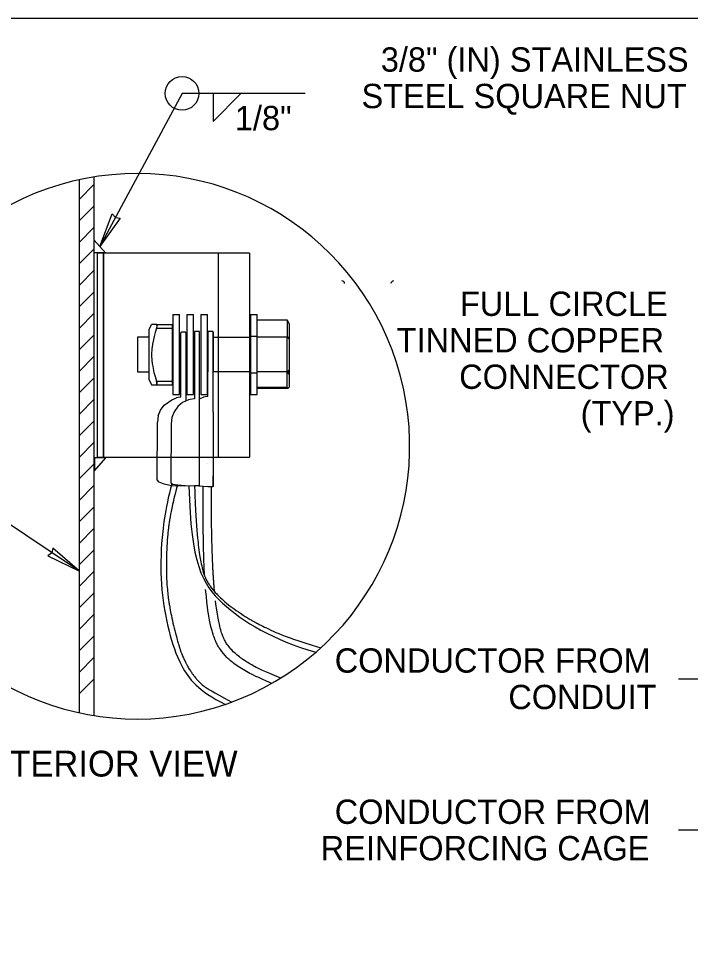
# Model space of a CAD drawing. Extents: x 99862 to 103680, y 99470 to 105076.
# Drawn here: x 101525 to 101968, y 104466 to 105076 of the extents above; entities that cross this region are included whole.
import ezdxf

# ---------------------------------------------------------------- set-up
doc = ezdxf.new("R2010")
doc.units = 0
for name, color, linetype in [('Level 1', 7, 'Continuous'), ('Level 10', 7, 'Continuous'), ('Level 11', 7, 'Continuous'), ('Level 12', 7, 'Continuous'), ('Level 14', 7, 'Continuous'), ('Level 15', 7, 'Continuous'), ('Level 18', 7, 'Continuous'), ('Level 2', 7, 'Continuous'), ('Level 20', 7, 'Continuous'), ('Level 21', 7, 'Continuous'), ('Level 3', 7, 'Continuous'), ('Level 34', 7, 'Continuous'), ('Level 4', 7, 'Continuous')]:
    doc.layers.add(name, color=color, linetype=linetype)

msp = doc.modelspace()

# ---------------------------------------------------------------- linework, layer by layer
at = {"layer": 'Level 1'}
for p, q in [((101577.19, 104921.26), (101577.21, 104921.26)), ((101577.19, 104921.26), (101577.19, 104786.96)), ((101581.33, 104921.26), (101581.33, 104786.96)), ((101656.72, 104921.26), (101656.72, 104786.96)), ((101677.39, 104921.26), (101677.39, 104786.96)), ((101677.39, 104843.2), (101653.49, 104843.2)), ((101577.21, 104786.96), (101577.19, 104786.96))]:
    msp.add_line(p, q, dxfattribs=at)
msp.add_lwpolyline([(99862, 102999.5), (103151, 102999.5), (103151, 105075.5), (99862, 105075.5)], close=True, dxfattribs=at)
for points in [[(101677.39, 104921.26), (101677.21, 104921.26), (101675.26, 104921.26), (101670.68, 104921.26), (101664.21, 104921.26), (101656.72, 104921.26), (101581.33, 104921.26), (101577.21, 104921.26), (101577.21, 104786.96), (101581.33, 104786.96), (101616.78, 104786.96)], [(101581.31, 104786.96), (101581.31, 104786.96), (101581.31, 104921.26), (101581.31, 104921.26)], [(101677.39, 104865.75), (101677.39, 104865.75), (101653.49, 104865.75)], [(101653.48, 104786.96), (101656.72, 104786.96), (101664.21, 104786.96), (101670.68, 104786.96), (101675.26, 104786.96), (101677.21, 104786.96), (101677.39, 104786.96)]]:
    msp.add_lwpolyline(points, dxfattribs=at)
at = {"layer": 'Level 10'}
for centre, start, end in [((101738.25, 104901.12), 0, 90), ((101772.28, 104901.12), 90, 180)]:
    msp.add_arc(centre, 1.8, start, end, dxfattribs=at)
at = {"layer": 'Level 11'}
for points in [[(101626.26, 104769.75), (101621.67, 104751.55), (101618.9, 104729.68), (101618.9, 104699.44), (101624.29, 104671.59), (101631.13, 104649.94), (101643.4, 104633.25), (101661.68, 104624.31)], [(101629.99, 104768.75), (101627.65, 104759.73), (101626.15, 104752.94), (101624.84, 104745.62), (101624.58, 104743.99), (101624.26, 104741.74), (101624.17, 104741.03), (101623.99, 104739.58), (101623.57, 104735.89), (101623.26, 104731.95), (101622.89, 104725.34), (101622.77, 104721.87), (101622.72, 104717.33), (101622.71, 104716.42), (101622.7, 104715.03), (101622.7, 104714.56), (101622.71, 104713.64), (101622.72, 104711.33), (101622.89, 104705.41), (101623.32, 104700.07), (101623.94, 104694.82), (101624.29, 104692.21), (101624.78, 104689.21), (101625.05, 104687.72), (101625.17, 104687.08), (101625.25, 104686.66), (101625.29, 104686.45), (101626.66, 104679.36), (101628.12, 104673.08), (101630.1, 104665.97), (101630.61, 104664.24), (101631.12, 104662.57), (101631.28, 104662.07), (101631.33, 104661.91), (101631.43, 104661.59), (101631.69, 104660.79), (101631.96, 104660), (101633.08, 104656.88), (101634.1, 104654.49), (101636.39, 104649.92), (101637.67, 104647.73), (101639.41, 104645.13), (101639.77, 104644.62), (101640.32, 104643.86), (101640.5, 104643.6), (101640.87, 104643.12), (101641.79, 104641.91), (101642.73, 104640.81), (101645.04, 104638.33), (101646.65, 104636.92), (101649.89, 104634.63), (101651.53, 104633.71), (101665.78, 104625.74)], [(101637.55, 104768.23), (101638.8, 104716.73), (101653.49, 104690.38), (101693.08, 104666.73), (101721.07, 104658.71)], [(101641.33, 104768.15), (101641.64, 104756.84), (101642.1, 104747.46), (101643.15, 104734.4), (101643.62, 104729.91), (101644.71, 104721.95), (101645.32, 104718.47), (101646.66, 104712.55), (101647.4, 104710.11), (101648.33, 104707.77), (101648.52, 104707.34), (101648.8, 104706.75), (101648.89, 104706.56), (101649.08, 104706.2), (101649.17, 104706.03), (101649.32, 104705.77), (101649.37, 104705.67), (101649.48, 104705.48), (101649.64, 104705.2), (101650.03, 104704.55), (101650.39, 104703.98), (101652.61, 104700.59), (101655.19, 104697.54), (101661.6, 104691.44), (101665.44, 104688.38), (101672.13, 104683.81), (101674.52, 104682.29), (101677.69, 104680.4), (101678.33, 104680.03), (101679.63, 104679.29), (101681.61, 104678.19), (101683.67, 104677.1), (101695.56, 104671.12), (101708.15, 104666.36), (101724.43, 104661.68)]]:
    msp.add_open_spline(points, degree=3, dxfattribs=at)
at = {"layer": 'Level 12'}
for p, q in [((101565.46, 104956.78), (101574.95, 104966.27)), ((101565.46, 104942.63), (101574.95, 104952.13)), ((101565.46, 104928.49), (101574.95, 104937.99)), ((101565.46, 104914.35), (101574.95, 104923.85)), ((101565.46, 104900.21), (101574.95, 104909.71)), ((101565.46, 104886.06), (101574.95, 104895.56)), ((101565.46, 104871.92), (101574.95, 104881.42)), ((101565.46, 104857.78), (101574.95, 104867.28)), ((101565.46, 104843.64), (101574.95, 104853.14)), ((101565.46, 104829.5), (101574.95, 104838.99)), ((101565.46, 104815.35), (101574.95, 104824.85)), ((101565.46, 104801.21), (101574.95, 104810.71)), ((101565.46, 104787.07), (101574.95, 104796.57)), ((101565.46, 104772.93), (101574.95, 104782.43)), ((101565.46, 104758.79), (101574.95, 104768.28)), ((101565.46, 104744.64), (101574.95, 104754.14)), ((101565.46, 104730.5), (101574.95, 104740)), ((101565.46, 104716.36), (101574.95, 104725.86)), ((101565.46, 104702.22), (101574.95, 104711.72)), ((101565.46, 104688.07), (101574.95, 104697.57)), ((101565.46, 104673.93), (101574.95, 104683.43)), ((101565.46, 104659.79), (101574.95, 104669.29)), ((101565.46, 104645.65), (101574.95, 104655.15)), ((101565.46, 104631.51), (101574.95, 104641))]:
    msp.add_line(p, q, dxfattribs=at)
at = {"layer": 'Level 14'}
for p, q in [((101650, 104869.26), (101650, 104865.81)), ((101644.27, 104825.35), (101647.2, 104826.49)), ((101653.49, 104816.67), (101653.48, 104767.74)), ((101616.78, 104786.96), (101655.1, 104786.96)), ((101653.48, 104767.74), (101653.48, 104774.66)), ((101649.99, 104767.74), (101653.48, 104767.74))]:
    msp.add_line(p, q, dxfattribs=at)
for points in [[(101650, 104826.96), (101650, 104859.91), (101650, 104864.54), (101650, 104867.95), (101650, 104869.26)], [(101650, 104843.05), (101650, 104843.24), (101650, 104843.86), (101650, 104844.89), (101650, 104846.28), (101650, 104848), (101650, 104849.96), (101650, 104852.09), (101650, 104854.32), (101650, 104856.55), (101650, 104858.7), (101650, 104860.69), (101650, 104862.45), (101650, 104863.89), (101650, 104864.97), (101650, 104865.65), (101650, 104865.9)], [(101650, 104865.9), (101650, 104865.72), (101650, 104865.09), (101650, 104864.07), (101650, 104862.67), (101650, 104860.96), (101650, 104858.99), (101650, 104856.86), (101650, 104854.63), (101650, 104852.4), (101650, 104850.25), (101650, 104848.26), (101650, 104846.51), (101650, 104845.06), (101650, 104843.98), (101650, 104843.3), (101650, 104843.05)], [(101653.04, 104869.71), (101650.45, 104869.71)], [(101653.49, 104816.67), (101653.49, 104852.5), (101653.49, 104857.81), (101653.49, 104862.69), (101653.49, 104866.52), (101653.49, 104868.81), (101653.49, 104869.26)], [(101653.49, 104869.26), (101653.49, 104867.81), (101653.49, 104864.65), (101653.49, 104860.18)], [(101653.49, 104865.9), (101653.49, 104865.72), (101653.49, 104865.09), (101653.49, 104864.07), (101653.49, 104862.67), (101653.49, 104860.96), (101653.49, 104858.99), (101653.49, 104856.86), (101653.49, 104854.63), (101653.49, 104852.4), (101653.49, 104850.25), (101653.49, 104848.26), (101653.49, 104846.51), (101653.49, 104845.06), (101653.49, 104843.98), (101653.49, 104843.3), (101653.49, 104843.05)], [(101650, 104852.5), (101650, 104843.05)], [(101650, 104826.96), (101648.25, 104826.74), (101647.2, 104826.49)], [(101650, 104782.92), (101650, 104782.93), (101650, 104782.93)], [(101642.47, 104768.32), (101644.03, 104768.08), (101650, 104767.75)]]:
    msp.add_lwpolyline(points, dxfattribs=at)
for centre, radius, start, end in [((101603.44, 104794.15), 179.4, 203.51773, 186.71627), ((101650.45, 104869.26), 0.45, 89.9972, 179.99451), ((101653.04, 104869.26), 0.45, 359.99451, 89.9972)]:
    msp.add_arc(centre, radius, start, end, dxfattribs=at)
at = {"layer": 'Level 15'}
for p, q in [((101633.05, 105026.26), (101578.87, 104925.57)), ((101714.08, 105026.26), (101633.05, 105026.26)), ((101671.83, 105026.26), (101653.43, 105007.85)), ((101653.43, 105026.26), (101653.43, 105007.85)), ((101641.13, 104825.43), (101638.33, 104824.92)), ((101626.36, 104812.98), (101625.91, 104808.83)), ((101565.44, 104712.04), (101512.03, 104747.72)), ((101959.87, 104641.25), (101974.26, 104641.25)), ((101959.87, 104541.79), (101974.26, 104541.79))]:
    msp.add_line(p, q, dxfattribs=at)
for points in [[(101578.87, 104925.57), (101587.09, 104947.08), (101589.22, 104944.73), (101592.34, 104944.25)], [(101565.44, 104712.04), (101548.05, 104727.13), (101547.29, 104724.06), (101544.76, 104722.16)]]:
    msp.add_lwpolyline(points, close=True, dxfattribs=at)
for points in [[(101641.13, 104869.26), (101641.13, 104868.41), (101641.13, 104856.69), (101641.13, 104852.32), (101641.13, 104847.16)], [(101641.13, 104866.29), (101641.13, 104857.21), (101641.13, 104856.4), (101641.13, 104855.2), (101641.13, 104853.65)], [(101644.17, 104869.71), (101641.58, 104869.71)], [(101644.62, 104834.81), (101644.62, 104835.2), (101644.62, 104836.01), (101644.62, 104837.21), (101644.62, 104838.76), (101644.62, 104840.6), (101644.62, 104842.65), (101644.62, 104844.83), (101644.62, 104847.07), (101644.62, 104849.28), (101644.62, 104851.37), (101644.62, 104853.26), (101644.62, 104854.88), (101644.62, 104856.16), (101644.62, 104869.26)], [(101641.13, 104855.43), (101641.13, 104825.43)], [(101644.62, 104768.08), (101644.62, 104772.06), (101644.62, 104836.01)], [(101637.2, 104824.61), (101633.43, 104822.87), (101630.24, 104820.23), (101627.83, 104816.86), (101626.36, 104812.98)], [(101638.33, 104824.92), (101637.59, 104824.78), (101637.2, 104824.61)], [(101625.91, 104808.83), (101625.75, 104770.07), (101626.9, 104769.34), (101630.19, 104768.72), (101635.16, 104768.28), (101644.62, 104768.08), (101641.13, 104768.08)]]:
    msp.add_lwpolyline(points, dxfattribs=at)
msp.add_circle((101633.05, 105026.26), 11.07, dxfattribs=at)
for centre, start, end in [((101641.58, 104869.26), 89.9971, 179.99929), ((101644.17, 104869.26), 359.99227, 89.9971)]:
    msp.add_arc(centre, 0.45, start, end, dxfattribs=at)
at = {"layer": 'Level 18'}
for p, q in [((101575.1, 104921.32), (101575.11, 104929.83)), ((101575.11, 104929.83), (101582.64, 104921.32)), ((101582.64, 104921.32), (101575.1, 104921.32)), ((101575.41, 104786.48), (101575.42, 104777.96)), ((101582.95, 104786.48), (101575.41, 104786.48)), ((101575.42, 104777.96), (101582.95, 104786.48))]:
    msp.add_line(p, q, dxfattribs=at)
at = {"layer": 'Level 2'}
for p, q in [((101626.88, 104880.78), (101631.29, 104880.78)), ((101636.09, 104880.78), (101640.51, 104880.78)), ((101645.3, 104880.78), (101649.72, 104880.78)), ((101677.99, 104880.78), (101682.41, 104880.78)), ((101677.99, 104842.47), (101682.41, 104842.47))]:
    msp.add_line(p, q, dxfattribs=at)
for points in [[(101626.88, 104880.78), (101626.88, 104879.5), (101626.88, 104875.76), (101626.88, 104869.94), (101626.88, 104862.61), (101626.88, 104854.48), (101626.88, 104846.35), (101626.88, 104839.01), (101626.88, 104833.19), (101626.88, 104829.45), (101626.88, 104828.17), (101631.29, 104828.17), (101631.29, 104829.45), (101631.29, 104833.19), (101631.29, 104839.01), (101631.29, 104846.35), (101631.29, 104854.48), (101631.29, 104862.61), (101631.29, 104869.94), (101631.29, 104875.76)], [(101631.29, 104875.76), (101631.29, 104875.76), (101631.29, 104879.5), (101631.29, 104880.78)], [(101636.09, 104880.78), (101636.09, 104879.5), (101636.09, 104875.76), (101636.09, 104869.94), (101636.09, 104862.61), (101636.09, 104854.48), (101636.09, 104846.35), (101636.09, 104839.01), (101636.09, 104833.19), (101636.09, 104829.45), (101636.09, 104828.17), (101640.51, 104828.17), (101640.51, 104829.45), (101640.51, 104833.19), (101640.51, 104839.01), (101640.51, 104846.35), (101640.51, 104854.48), (101640.51, 104862.61), (101640.51, 104869.94), (101640.51, 104875.76), (101640.51, 104879.5), (101640.51, 104880.78)], [(101645.3, 104880.78), (101645.3, 104879.5), (101645.3, 104875.76), (101645.3, 104869.94), (101645.3, 104862.61), (101645.3, 104854.48), (101645.3, 104846.35), (101645.3, 104839.01), (101645.3, 104833.19), (101645.3, 104829.45), (101645.3, 104828.17), (101649.72, 104828.17), (101649.72, 104829.45), (101649.72, 104833.19), (101649.72, 104839.01), (101649.72, 104846.35), (101649.72, 104854.48), (101649.72, 104862.61), (101649.72, 104869.94), (101649.72, 104875.76), (101649.72, 104879.5), (101649.72, 104880.78)], [(101677.99, 104880.78), (101677.99, 104879.5), (101677.99, 104875.76), (101677.99, 104869.94), (101677.99, 104862.61), (101677.99, 104854.48), (101677.99, 104846.35), (101677.99, 104839.01)], [(101677.99, 104839.01), (101677.99, 104839.01), (101677.99, 104833.19), (101677.99, 104829.45), (101677.99, 104828.17), (101682.41, 104828.17), (101682.41, 104829.45), (101682.41, 104833.19), (101682.41, 104839.01), (101682.41, 104846.35), (101682.41, 104854.48), (101682.41, 104862.61), (101682.41, 104869.94), (101682.41, 104875.76), (101682.41, 104879.5), (101682.41, 104880.78)], [(101677.99, 104866.48), (101677.99, 104866.48), (101682.41, 104866.48), (101682.41, 104866.48)]]:
    msp.add_lwpolyline(points, dxfattribs=at)
at = {"layer": 'Level 20'}
for p, q in [((101565.46, 104618.82), (101565.46, 104969.48)), ((101574.95, 104971.27), (101574.95, 104617.03))]:
    msp.add_line(p, q, dxfattribs=at)
at = {"layer": 'Level 21'}
for p, q in [((101621.25, 104821.14), (101626.4, 104824.79)), ((101626.4, 104824.79), (101629.34, 104825.93)), ((101617.36, 104814.14), (101616.91, 104810.11))]:
    msp.add_line(p, q, dxfattribs=at)
for points in [[(101632.14, 104826.4), (101632.14, 104859.34), (101632.14, 104863.97), (101632.14, 104867.39), (101632.14, 104868.69)], [(101635.18, 104869.14), (101632.59, 104869.14)], [(101635.63, 104868.69), (101635.63, 104867.39), (101635.63, 104863.97), (101635.62, 104823.74)], [(101632.14, 104826.4), (101630.39, 104826.18), (101629.34, 104825.93)], [(101617.36, 104814.14), (101618.84, 104817.9), (101621.25, 104821.14)], [(101634.83, 104767.86), (101626.16, 104768.24), (101621.19, 104769.17), (101617.9, 104770.5), (101616.75, 104772.05), (101616.91, 104810.11)]]:
    msp.add_lwpolyline(points, dxfattribs=at)
for centre, start, end in [((101632.59, 104868.69), 89.9972, 179.99451), ((101635.18, 104868.69), 359.99451, 89.9972)]:
    msp.add_arc(centre, 0.45, start, end, dxfattribs=at)
at = {"layer": 'Level 3'}
for p, q in [((101616.21, 104871.86), (101616.17, 104871.86)), ((101616.21, 104871.86), (101626.48, 104871.86)), ((101616.17, 104837.09), (101616.21, 104837.09))]:
    msp.add_line(p, q, dxfattribs=at)
for points in [[(101611.45, 104837.89), (101611.45, 104838.7), (101611.45, 104841.05), (101611.45, 104844.72), (101611.45, 104849.35), (101611.45, 104854.48), (101611.45, 104859.6), (101611.45, 104864.23), (101611.45, 104867.9), (101611.45, 104870.25), (101611.45, 104871.07), (101613.02, 104874.27)], [(101616.17, 104874.27), (101616.3, 104874.23), (101616.37, 104874.16), (101616.4, 104874.08), (101616.44, 104874.01), (101616.48, 104873.8), (101616.49, 104873.56), (101616.49, 104873.54), (101616.47, 104873.26), (101616.43, 104872.91), (101616.4, 104872.78), (101616.37, 104872.61), (101616.27, 104872.19), (101616.17, 104871.86), (101615.33, 104868.94), (101614.61, 104866.45), (101613.52, 104861.23), (101613.48, 104860.9), (101613.17, 104858.49), (101613.03, 104854.48), (101612.99, 104853.42), (101613.44, 104848.28), (101613.48, 104848.05), (101614.54, 104842.76), (101614.9, 104841.36), (101615.29, 104840.07), (101616.17, 104837.09), (101616.29, 104836.67), (101616.36, 104836.38), (101616.4, 104836.17), (101616.43, 104836), (101616.48, 104835.67), (101616.49, 104835.39), (101616.49, 104835.37), (101616.47, 104835.13), (101616.43, 104834.93), (101616.41, 104834.87), (101616.37, 104834.8), (101616.27, 104834.71), (101616.17, 104834.68), (101616.17, 104834.68)], [(101616.21, 104874.27), (101615.36, 104874.27), (101614.64, 104874.27), (101613.55, 104874.27), (101613.51, 104874.27), (101613.2, 104874.27), (101613.05, 104874.27), (101613.02, 104874.27)], [(101616.21, 104874.27), (101626.48, 104874.27), (101626.48, 104874.08), (101626.48, 104873.56), (101626.48, 104872.78), (101626.48, 104871.86), (101626.48, 104837.09), (101626.48, 104836.17), (101626.48, 104835.39), (101626.48, 104834.87), (101626.48, 104834.68)], [(101616.52, 104873.56), (101616.52, 104873.58), (101616.51, 104873.82), (101616.47, 104874.03), (101616.44, 104874.08), (101616.41, 104874.15), (101616.31, 104874.24), (101616.21, 104874.27)], [(101611.45, 104837.89), (101613.03, 104834.68), (101613.2, 104834.68), (101613.59, 104834.68), (101614.09, 104834.68), (101615.36, 104834.68), (101615.73, 104834.68), (101616.21, 104834.68), (101626.48, 104834.68)], [(101616.44, 104836.17), (101616.41, 104836.34), (101616.31, 104836.76), (101616.21, 104837.09), (101626.48, 104837.09)], [(101616.21, 104834.68), (101616.33, 104834.72), (101616.4, 104834.79), (101616.44, 104834.88), (101616.47, 104834.94), (101616.51, 104835.15), (101616.52, 104835.39), (101616.52, 104835.41), (101616.51, 104835.69), (101616.47, 104836.04), (101616.44, 104836.17), (101616.44, 104836.17)]]:
    msp.add_lwpolyline(points, dxfattribs=at)
at = {"layer": 'Level 34'}
for points, degree in [([(101647.89, 104709.11), (101647.6, 104714.24), (101647.28, 104722.43), (101646.91, 104742.25), (101646.92, 104754.24), (101646.83, 104767.93)], 3), ([(101654.38, 104698.87), (101652.15, 104724.43), (101652.43, 104767.74)], 2), ([(101692.12, 104638.21), (101681.9, 104642.56), (101677.02, 104645), (101667.16, 104651.08), (101662.68, 104654.86), (101657.73, 104661.07), (101656.38, 104663.23), (101655.22, 104665.76), (101655.1, 104666.04), (101654.86, 104666.61), (101654.5, 104667.48), (101654.16, 104668.41), (101653.5, 104670.34), (101653.08, 104671.72), (101651.11, 104679.13), (101649.89, 104686.66), (101648.57, 104700.01)], 3), ([(101697.99, 104641.7), (101686.22, 104646.49), (101680.63, 104649.2), (101673.38, 104653.67), (101671.06, 104655.34), (101667.04, 104658.74), (101665.34, 104660.47), (101662.52, 104664.02), (101661.41, 104665.82), (101659.73, 104669.48), (101658.94, 104671.79), (101657.47, 104677.3), (101656.81, 104680.47), (101655.8, 104686.93), (101655.45, 104689.54), (101655.1, 104692.53)], 3)]:
    msp.add_open_spline(points, degree=degree, dxfattribs=at)
at = {"layer": 'Level 4'}
for p, q in [((101702.24, 104865.91), (101703.44, 104865.91)), ((101603.68, 104843.05), (101611.45, 104843.05)), ((101702.24, 104843.05), (101682.41, 104843.05)), ((101703.44, 104843.05), (101702.24, 104843.05))]:
    msp.add_line(p, q, dxfattribs=at)
for points in [[(101682.41, 104843.05), (101682.41, 104843.05), (101682.41, 104865.91), (101682.41, 104877.33), (101702.24, 104877.33), (101703.44, 104874.56), (101703.44, 104864.52)], [(101702.24, 104877.33), (101702.24, 104865.91), (101703.44, 104864.52)], [(101611.45, 104865.91), (101603.68, 104865.91), (101603.68, 104865.04), (101603.68, 104862.56), (101603.68, 104858.85), (101603.68, 104854.48), (101603.68, 104850.1), (101603.68, 104846.39), (101603.68, 104843.92), (101603.68, 104843.05)], [(101703.44, 104841.66), (101702.24, 104843.05), (101702.24, 104865.91), (101682.41, 104865.91)], [(101703.44, 104864.52), (101703.44, 104841.66), (101703.44, 104833.01), (101702.76, 104832.22), (101682.41, 104832.22), (101682.41, 104843.05)], [(101703.44, 104844.44), (101702.24, 104843.05), (101702.24, 104843.05)], [(101702.76, 104832.22), (101702.24, 104832.82), (101702.24, 104843.05), (101702.24, 104843.05)], [(101702.24, 104832.82), (101682.41, 104832.82), (101682.41, 104832.82)]]:
    msp.add_lwpolyline(points, dxfattribs=at)

# ---------------------------------------------------------------- texts
at = {"layer": 'Level 20'}
for s, height, p in [('3/8" (IN) STAINLESS ', 16, (101763.85, 105040.55)), ('STEEL SQUARE NUT', 16, (101751.17, 105016.55)), ('1/8"', 16, (101667.81, 105002.06)), ('FULL CIRCLE', 16, (101815.95, 104879.9)), (' TINNED COPPER ', 16, (101768.35, 104855.9)), ('CONNECTOR', 16, (101815.43, 104831.9)), ('(TYP.)', 16, (101895.36, 104807.9)), ('CONDUCTOR FROM', 16, (101733.52, 104645.25)), ('CONDUIT', 16, (101847.79, 104621.25)), ('INTERIOR VIEW', 17, (101496.59, 104576.93)), ('CONDUCTOR FROM', 16, (101733.52, 104545.79)), ('REINFORCING CAGE', 16, (101724.3, 104521.79))]:
    msp.add_text(s, height=height, dxfattribs=at).set_placement(p)

doc.saveas('drawing.dxf')
